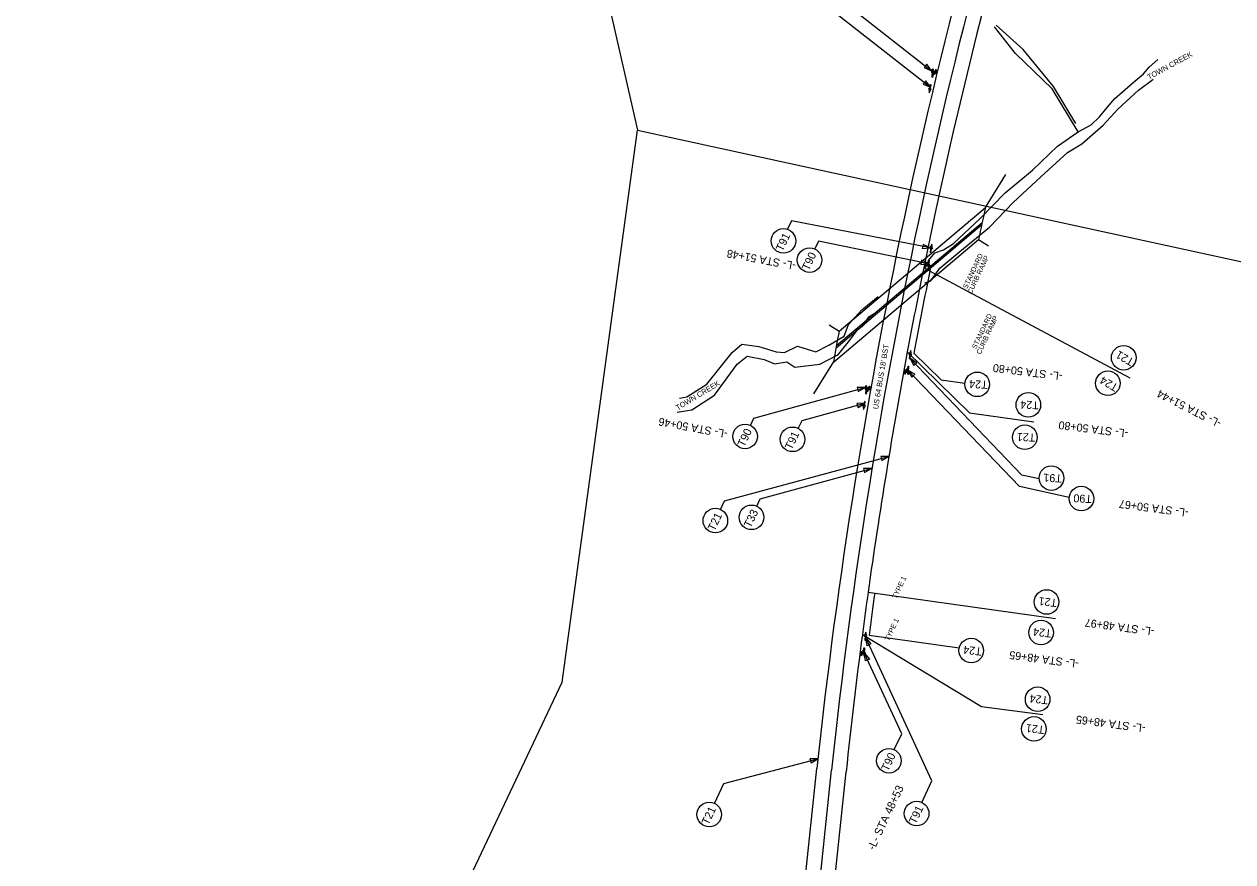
# Model space of a CAD drawing. Extents: x 553958 to 562499, y 493978 to 516388.
# Drawn here: x 556547 to 557453, y 505302 to 505930 of the extents above; entities that cross this region are included whole.
import ezdxf

# ---------------------------------------------------------------- set-up
doc = ezdxf.new("R2010")
doc.units = 0
for name, color, linetype in [('Default', 7, 'Continuous'), ('Prop Approach Slab', 7, 'Continuous'), ('Prop Conc 4in Sidewalk', 7, 'Continuous'), ('Prop EOT', 7, 'Continuous'), ('Prop Erosion Rip Rap Class II Label', 7, 'Continuous'), ('Prop Guardrail', 7, 'Continuous'), ('Prop Guardrail Anchor Unit CELL', 7, 'Continuous'), ('Prop Horizontal Alignment Tick Small', 7, 'Continuous'), ('Prop Superelevation Label', 7, 'Continuous'), ('Raster_Level_0', 7, 'Continuous'), ('Sheet Plan CELL', 7, 'Continuous'), ('Sheet Plot Border Inside CELL', 7, 'Continuous')]:
    doc.layers.add(name, color=color, linetype=linetype)

msp = doc.modelspace()

# ---------------------------------------------------------------- linework, layer by layer
at = {"layer": 'Default'}
for p, q in [((557267.43, 505792.37), (557282.76, 505817.09)), ((557157.69, 505699.67), (557267.43, 505792.37)), ((557155.38, 505687.25), (557264.62, 505779.52)), ((557155.67, 505688.8), (557264.96, 505781.12)), ((557153.4, 505676.41), (557262.19, 505768.31)), ((557262.19, 505768.31), (557269.79, 505763.6)), ((557150.22, 505704.3), (557157.69, 505699.67)), ((557138.72, 505652.73), (557153.4, 505676.41))]:
    msp.add_line(p, q, dxfattribs=at)
for centre, radius, start, end in [((561145.87, 504935.36), 3972, 167.53963, 167.89484), ((561116.74, 504957.58), 4028, 169.38359, 169.72001)]:
    msp.add_arc(centre, radius, start, end, dxfattribs=at)
at = {"layer": 'Prop Approach Slab'}
for p, q in [((557121.98, 505782.31), (557118.98, 505775.98)), ((557226.11, 505762.03), (557121.98, 505782.31)), ((557142.28, 505767.11), (557139.49, 505761.21)), ((557223.63, 505750.23), (557142.28, 505767.11)), ((557221.13, 505747.07), (557375.74, 505664.58)), ((557208.83, 505684.06), (557255.39, 505638.46)), ((557213.75, 505683.15), (557234.23, 505663.09)), ((557234.23, 505663.09), (557252.07, 505660.57)), ((557255.39, 505638.46), (557303.67, 505631.65)), ((557179.45, 505503.99), (557319.85, 505484.2)), ((557175.16, 505472.41), (557264.56, 505418.34)), ((557180.12, 505471.76), (557247.75, 505462.22)), ((557264.56, 505418.34), (557310.51, 505412.3))]:
    msp.add_line(p, q, dxfattribs=at)
at = {"layer": 'Prop EOT'}
for centre, start, end in [((561130.03, 504951.7), 168.49878, 169.42078), ((561134.93, 504950.71), 168.49878, 169.41963), ((561130.03, 504951.7), 172.04172, 172.49947), ((561134.99, 504951.05), 172.04229, 172.49947)]:
    msp.add_arc(centre, 3989, start, end, dxfattribs=at)
at = {"layer": 'Prop Erosion Rip Rap Class II Label'}
for points in [[(557510.24, 505740.54), (557854.59, 506431.05), (557889.73, 506539.36), (557425.46, 506933.59), (557046.6, 506628.46), (556899.98, 506318.25), (557006.57, 505850.3)], [(556922.59, 504396.31), (556546.8, 504844.44), (556803.39, 505126.33), (556950.01, 505436.53), (557006.57, 505850.3), (557510.24, 505740.54), (557485.82, 505175.14), (557082.56, 504320.7)]]:
    msp.add_lwpolyline(points, close=True, dxfattribs=at)
at = {"layer": 'Prop Guardrail'}
msp.add_line((557329.01, 505833.44), (557339.73, 505839.98), dxfattribs=at)
for points in [[(557335.2, 505855.15), (557318.48, 505882.86), (557295.62, 505910.67), (557275.53, 505929.04)], [(557224.65, 505752.62), (557229.44, 505758.43), (557236.01, 505760.45), (557243.43, 505765.25), (557263.41, 505784.12), (557282.31, 505803.32), (557302.6, 505820.21), (557321.39, 505838.21), (557336.85, 505849.11), (557317.41, 505881.09), (557290.05, 505907.77), (557274.13, 505927.57)], [(557336.85, 505849.11), (557346.59, 505854.26), (557352.92, 505860.11), (557358.68, 505867.34), (557364.34, 505874.04), (557370.09, 505879.01), (557378.2, 505886.08), (557382.54, 505889.59), (557385.91, 505892.34), (557390.17, 505897.4), (557396.51, 505903.31)], [(557339.73, 505839.98), (557355.53, 505854.05), (557366.65, 505865.91), (557382.17, 505880.3), (557392.8, 505888.25), (557393.19, 505888.6)], [(557221.92, 505735.81), (557226.55, 505737.34), (557233.13, 505746.89), (557248.24, 505759.3), (557270.35, 505777.55), (557288.27, 505795.98), (557308.94, 505815.28), (557329.01, 505833.44)], [(557077.55, 505683.54), (557084.84, 505689.76), (557097.49, 505688.05), (557110.48, 505684.17), (557116.79, 505683.52), (557126.52, 505688.35), (557140.16, 505684.2), (557150.11, 505689.11), (557161.38, 505695.79), (557164.82, 505704.7), (557169.67, 505710.11), (557174.65, 505715.49), (557186.92, 505725.65)], [(557081.24, 505674.86), (557088.86, 505680.94), (557101.51, 505678.39), (557109.34, 505675.15), (557118.47, 505676.53), (557124.62, 505672.58), (557143.22, 505674.95), (557156.24, 505681.56), (557156.45, 505681.36), (557165.79, 505692.89), (557171.41, 505700.52), (557176.2, 505704.36), (557179.88, 505710.38), (557184.61, 505713.09)], [(557036.33, 505638.98), (557047.2, 505640.77), (557064.25, 505651.6), (557081.24, 505674.86)], [(557038.03, 505649.41), (557043.56, 505650.32), (557058.48, 505659.79), (557077.55, 505683.54)]]:
    msp.add_lwpolyline(points, dxfattribs=at)
at = {"layer": 'Prop Horizontal Alignment Tick Small'}
for p, q in [((557227.05, 505894.79), (557227.28, 505894.73)), ((557227.05, 505894.79), (557227.28, 505894.73)), ((557227.46, 505891.19), (557227.73, 505892.84)), ((557227.73, 505892.84), (557228.87, 505894.62)), ((557228, 505892.58), (557227.82, 505891.5)), ((557227.82, 505891.5), (557228.95, 505892.29)), ((557229.07, 505894.5), (557228, 505892.81)), ((557228, 505892.81), (557228.77, 505892.95)), ((557229, 505892.75), (557228, 505892.58)), ((557228.08, 505894.55), (557228.32, 505894.49)), ((557228.08, 505894.55), (557228.32, 505894.49)), ((557228.77, 505892.95), (557228.78, 505893.6)), ((557228.78, 505893.6), (557229.02, 505893.59)), ((557228.87, 505894.62), (557229.08, 505894.52)), ((557228.95, 505892.29), (557228.88, 505891.99)), ((557229.02, 505893.59), (557229, 505892.75)), ((557229.43, 505894.24), (557229.67, 505894.18)), ((557229.43, 505894.24), (557229.67, 505894.18)), ((557230.46, 505894), (557230.7, 505893.95)), ((557230.46, 505894), (557230.7, 505893.95)), ((557227.21, 505890.7), (557227.06, 505890.74)), ((557227.21, 505890.7), (557227.06, 505890.74)), ((557227.78, 505891.21), (557227.46, 505891.19)), ((557228.88, 505891.99), (557227.78, 505891.21)), ((557228.16, 505890.49), (557228.01, 505890.52)), ((557228.16, 505890.49), (557228.01, 505890.52)), ((557222.24, 505748.91), (557222, 505748.95)), ((557222.24, 505748.91), (557222, 505748.95)), ((557223.28, 505748.72), (557223.04, 505748.77)), ((557223.28, 505748.72), (557223.04, 505748.77)), ((557223.63, 505750.23), (557224.62, 505750.46)), ((557223.66, 505749.39), (557223.63, 505750.23)), ((557223.86, 505748.37), (557223.64, 505748.46)), ((557224.75, 505751.54), (557223.66, 505750.69)), ((557223.66, 505750.69), (557223.72, 505750.99)), ((557223.66, 505748.48), (557224.64, 505750.22)), ((557223.9, 505749.4), (557223.66, 505749.39)), ((557223.72, 505750.99), (557224.78, 505751.83)), ((557224.9, 505750.21), (557223.86, 505748.37)), ((557224.64, 505750.22), (557223.88, 505750.05)), ((557223.88, 505750.05), (557223.9, 505749.4)), ((557224.37, 505752.53), (557224.52, 505752.51)), ((557224.37, 505752.53), (557224.52, 505752.51)), ((557224.64, 505748.48), (557224.4, 505748.52)), ((557224.64, 505748.48), (557224.4, 505748.52)), ((557224.62, 505750.46), (557224.75, 505751.54)), ((557224.78, 505751.83), (557225.1, 505751.86)), ((557225.1, 505751.86), (557224.9, 505750.21)), ((557225.33, 505752.36), (557225.48, 505752.34)), ((557225.33, 505752.36), (557225.48, 505752.34)), ((557225.69, 505748.29), (557225.45, 505748.34)), ((557225.69, 505748.29), (557225.45, 505748.34)), ((557206.92, 505669.12), (557206.68, 505669.16)), ((557206.92, 505669.12), (557206.68, 505669.16)), ((557207.97, 505668.95), (557207.73, 505668.99)), ((557207.97, 505668.95), (557207.73, 505668.99)), ((557208.3, 505670.46), (557209.29, 505670.69)), ((557208.34, 505669.62), (557208.3, 505670.46)), ((557209.41, 505671.78), (557208.33, 505670.92)), ((557208.33, 505670.92), (557208.38, 505671.22)), ((557208.55, 505668.6), (557208.33, 505668.69)), ((557208.58, 505669.63), (557208.34, 505669.62)), ((557208.35, 505668.71), (557209.31, 505670.46)), ((557208.38, 505671.22), (557209.43, 505672.07)), ((557209.31, 505670.46), (557208.55, 505670.28)), ((557209.58, 505670.45), (557208.55, 505668.6)), ((557208.55, 505670.28), (557208.58, 505669.63)), ((557209.01, 505672.77), (557209.16, 505672.75)), ((557209.01, 505672.77), (557209.16, 505672.75)), ((557209.33, 505668.72), (557209.09, 505668.76)), ((557209.33, 505668.72), (557209.09, 505668.76)), ((557209.29, 505670.69), (557209.41, 505671.78)), ((557209.43, 505672.07), (557209.75, 505672.11)), ((557209.75, 505672.11), (557209.58, 505670.45)), ((557209.97, 505672.61), (557210.12, 505672.58)), ((557209.97, 505672.61), (557210.12, 505672.58)), ((557210.38, 505668.55), (557210.14, 505668.59)), ((557210.38, 505668.55), (557210.14, 505668.59)), ((557177.18, 505657.42), (557177.42, 505657.38)), ((557177.18, 505657.42), (557177.42, 505657.38)), ((557177.98, 505655.52), (557179, 505657.37)), ((557178.22, 505657.25), (557178.46, 505657.21)), ((557178.22, 505657.25), (557178.46, 505657.21)), ((557179.21, 505657.26), (557178.25, 505655.51)), ((557179, 505657.37), (557179.22, 505657.28)), ((557179.59, 505657.02), (557179.83, 505656.98)), ((557179.59, 505657.02), (557179.83, 505656.98)), ((557180.64, 505656.85), (557180.88, 505656.81)), ((557180.64, 505656.85), (557180.88, 505656.81)), ((557177.58, 505653.36), (557177.43, 505653.39)), ((557177.58, 505653.36), (557177.43, 505653.39)), ((557177.8, 505653.86), (557177.98, 505655.52)), ((557178.13, 505653.9), (557177.8, 505653.86)), ((557179.18, 505654.75), (557178.13, 505653.9)), ((557178.27, 505655.28), (557178.15, 505654.19)), ((557178.15, 505654.19), (557179.23, 505655.05)), ((557178.25, 505655.51), (557179.01, 505655.69)), ((557179.25, 505655.51), (557178.27, 505655.28)), ((557178.54, 505653.2), (557178.39, 505653.22)), ((557178.54, 505653.2), (557178.39, 505653.22)), ((557178.98, 505656.34), (557179.21, 505656.35)), ((557179.01, 505655.69), (557178.98, 505656.34)), ((557179.23, 505655.05), (557179.18, 505654.75)), ((557179.21, 505656.35), (557179.25, 505655.51)), ((557174.01, 505457.97), (557173.77, 505458)), ((557174.01, 505457.97), (557173.77, 505458)), ((557175.06, 505457.84), (557174.82, 505457.87)), ((557175.06, 505457.84), (557174.82, 505457.87)), ((557175.33, 505459.37), (557176.31, 505459.65)), ((557175.41, 505458.53), (557175.33, 505459.37)), ((557176.37, 505460.74), (557175.34, 505459.83)), ((557175.34, 505459.83), (557175.37, 505460.13)), ((557175.37, 505460.13), (557176.38, 505461.02)), ((557175.64, 505458.55), (557175.41, 505458.53)), ((557175.66, 505457.52), (557175.44, 505457.6)), ((557175.45, 505457.62), (557176.33, 505459.41)), ((557176.33, 505459.41), (557175.59, 505459.2)), ((557175.59, 505459.2), (557175.64, 505458.55)), ((557176.6, 505459.41), (557175.66, 505457.52)), ((557175.93, 505461.71), (557176.09, 505461.69)), ((557175.93, 505461.71), (557176.09, 505461.69)), ((557176.44, 505457.68), (557176.2, 505457.71)), ((557176.44, 505457.68), (557176.2, 505457.71)), ((557176.31, 505459.65), (557176.37, 505460.74)), ((557176.38, 505461.02), (557176.7, 505461.08)), ((557176.7, 505461.08), (557176.6, 505459.41)), ((557176.9, 505461.59), (557177.05, 505461.57)), ((557176.9, 505461.59), (557177.05, 505461.57)), ((557177.49, 505457.55), (557177.25, 505457.58)), ((557177.49, 505457.55), (557177.25, 505457.58))]:
    msp.add_line(p, q, dxfattribs=at)
for points in [[(557226.83, 505881.26), (557226.03, 505880.77), (557226.68, 505884.11), (557226.06, 505884.23), (557225.41, 505880.89), (557224.85, 505881.65), (557225.22, 505878.28)], [(557226.83, 505881.26), (557226.03, 505880.77), (557226.68, 505884.11), (557226.06, 505884.23), (557225.41, 505880.89), (557224.85, 505881.65), (557225.22, 505878.28)], [(557225.71, 505761.78), (557226.51, 505762.28), (557225.86, 505758.94), (557226.48, 505758.82), (557227.13, 505762.15), (557227.69, 505761.4), (557227.32, 505764.77)], [(557225.71, 505761.78), (557226.51, 505762.28), (557225.86, 505758.94), (557226.48, 505758.82), (557227.13, 505762.15), (557227.69, 505761.4), (557227.32, 505764.77)], [(557209.97, 505682.05), (557210.75, 505682.57), (557210.24, 505679.21), (557210.87, 505679.12), (557211.38, 505682.48), (557211.96, 505681.75), (557211.45, 505685.1)], [(557209.97, 505682.05), (557210.75, 505682.57), (557210.24, 505679.21), (557210.87, 505679.12), (557211.38, 505682.48), (557211.96, 505681.75), (557211.45, 505685.1)], [(557177.52, 505643.92), (557176.74, 505643.4), (557177.3, 505646.75), (557176.67, 505646.86), (557176.11, 505643.51), (557175.53, 505644.25), (557176, 505640.89)], [(557177.52, 505643.92), (557176.74, 505643.4), (557177.3, 505646.75), (557176.67, 505646.86), (557176.11, 505643.51), (557175.53, 505644.25), (557176, 505640.89)], [(557176.47, 505471.02), (557177.22, 505471.58), (557176.87, 505468.2), (557177.5, 505468.13), (557177.86, 505471.51), (557178.48, 505470.81), (557177.81, 505474.13)], [(557176.47, 505471.02), (557177.22, 505471.58), (557176.87, 505468.2), (557177.5, 505468.13), (557177.86, 505471.51), (557178.48, 505470.81), (557177.81, 505474.13)]]:
    msp.add_lwpolyline(points, close=True, dxfattribs=at)
for centre, radius, start, end in [((557227.61, 505890.61), 0.563, 167.06052, 347.06052), ((557227.61, 505890.61), 0.563, 167.06052, 347.06052), ((557227.61, 505890.61), 0.41, 347.06052, 167.06052), ((557224.92, 505752.44), 0.563, 349.86585, 169.86585), ((557224.92, 505752.44), 0.563, 349.86585, 169.86585), ((557224.92, 505752.44), 0.41, 169.86585, 349.86585), ((557209.57, 505672.68), 0.563, 350.49881, 170.49881), ((557209.57, 505672.68), 0.563, 350.49881, 170.49881), ((557209.57, 505672.68), 0.41, 170.49881, 350.49881), ((557177.99, 505653.29), 0.563, 170.49881, 350.49881), ((557177.99, 505653.29), 0.563, 170.49881, 350.49881), ((557177.99, 505653.29), 0.41, 350.49881, 170.49881), ((557176.49, 505461.64), 0.563, 353.09103, 173.09103), ((557176.49, 505461.64), 0.563, 353.09103, 173.09103), ((557176.49, 505461.64), 0.41, 173.09103, 353.09103)]:
    msp.add_arc(centre, radius, start, end, dxfattribs=at)
for centre, major_axis, ratio, start_param, end_param in [((557227.68, 505894.64), (0.33, 1.46), 0.435841, 1.570796, 4.712389), ((557227.68, 505894.64), (0.33, 1.46), 0.435841, 4.712389, 7.853982), ((557227.68, 505894.64), (0.28, 1.22), 0.325967, 1.570796, 4.712389), ((557227.68, 505894.64), (0.28, 1.22), 0.325967, 4.712389, 7.853982), ((557230.07, 505894.09), (0.33, 1.46), 0.435841, 1.570796, 4.712389), ((557230.07, 505894.09), (0.33, 1.46), 0.435841, 4.712389, 7.853982), ((557230.07, 505894.09), (0.28, 1.22), 0.325967, 1.570796, 4.712389), ((557230.07, 505894.09), (0.28, 1.22), 0.325967, 4.712389, 7.853982), ((557222.64, 505748.84), (-0.26, -1.47), 0.435841, 4.712389, 7.853982), ((557222.64, 505748.84), (-0.26, -1.47), 0.435841, 1.570796, 4.712389), ((557222.64, 505748.84), (-0.22, -1.23), 0.325967, 4.712389, 7.853982), ((557222.64, 505748.84), (-0.22, -1.23), 0.325967, 1.570796, 4.712389), ((557225.04, 505748.41), (-0.26, -1.47), 0.435841, 4.712389, 7.853982), ((557225.04, 505748.41), (-0.26, -1.47), 0.435841, 1.570796, 4.712389), ((557225.04, 505748.41), (-0.22, -1.23), 0.325967, 4.712389, 7.853982), ((557225.04, 505748.41), (-0.22, -1.23), 0.325967, 1.570796, 4.712389), ((557207.32, 505669.06), (-0.25, -1.47), 0.435841, 4.712389, 7.853982), ((557207.32, 505669.06), (-0.25, -1.47), 0.435841, 1.570796, 4.712389), ((557207.32, 505669.06), (-0.21, -1.23), 0.325967, 4.712389, 7.853982), ((557207.32, 505669.06), (-0.21, -1.23), 0.325967, 1.570796, 4.712389), ((557209.74, 505668.65), (-0.25, -1.47), 0.435841, 4.712389, 7.853982), ((557209.74, 505668.65), (-0.25, -1.47), 0.435841, 1.570796, 4.712389), ((557209.74, 505668.65), (-0.21, -1.23), 0.325967, 4.712389, 7.853982), ((557209.74, 505668.65), (-0.21, -1.23), 0.325967, 1.570796, 4.712389), ((557177.82, 505657.32), (0.25, 1.47), 0.435841, 1.570796, 4.712389), ((557177.82, 505657.32), (0.25, 1.47), 0.435841, 4.712389, 7.853982), ((557177.82, 505657.32), (0.21, 1.23), 0.325967, 1.570796, 4.712389), ((557177.82, 505657.32), (0.21, 1.23), 0.325967, 4.712389, 7.853982), ((557180.23, 505656.91), (0.25, 1.47), 0.435841, 1.570796, 4.712389), ((557180.23, 505656.91), (0.25, 1.47), 0.435841, 4.712389, 7.853982), ((557180.23, 505656.91), (0.21, 1.23), 0.325967, 1.570796, 4.712389), ((557180.23, 505656.91), (0.21, 1.23), 0.325967, 4.712389, 7.853982), ((557174.41, 505457.92), (-0.18, -1.48), 0.435841, 4.712389, 7.853982), ((557174.41, 505457.92), (-0.18, -1.48), 0.435841, 1.570796, 4.712389), ((557174.41, 505457.92), (-0.15, -1.24), 0.325967, 4.712389, 7.853982), ((557174.41, 505457.92), (-0.15, -1.24), 0.325967, 1.570796, 4.712389), ((557176.84, 505457.63), (-0.18, -1.48), 0.435841, 4.712389, 7.853982), ((557176.84, 505457.63), (-0.18, -1.48), 0.435841, 1.570796, 4.712389), ((557176.84, 505457.63), (-0.15, -1.24), 0.325967, 4.712389, 7.853982), ((557176.84, 505457.63), (-0.15, -1.24), 0.325967, 1.570796, 4.712389)]:
    msp.add_ellipse(centre, major_axis=major_axis, ratio=ratio, start_param=start_param, end_param=end_param, dxfattribs=at)
at = {"layer": 'Raster_Level_0'}
msp.add_line((557110.08, 504972.34), (557152.03, 505370.68), dxfattribs=at)
msp.add_arc((561130.03, 504951.7), 4000, 161.63616, 173.98751, dxfattribs=at)
at = {"layer": 'Sheet Plan CELL'}
for points in [[(557148.39, 505963.62), (557141.4, 505948.88), (557226.34, 505882.38)], [(557173.37, 505958.65), (557165.84, 505942.7), (557227.05, 505894.79)], [(557307.66, 505588.94), (557294.62, 505591.77), (557210.87, 505679.12)], [(557330.14, 505575.04), (557293.01, 505583.1), (557209.27, 505670.45)], [(557091.19, 505629.05), (557093.75, 505634.47), (557177.18, 505657.42)], [(557126.99, 505626.77), (557129.91, 505632.57), (557177.1, 505645.56)], [(557068.88, 505566.04), (557071.87, 505572.6), (557195.02, 505605.77)], [(557095.97, 505568.45), (557098.53, 505573.87), (557181.96, 505596.83)], [(557219.78, 505346.48), (557227.34, 505362.57), (557177.68, 505469.82)], [(557199.01, 505386.04), (557204.64, 505397.85), (557176.56, 505458.51)], [(557064.3, 505345.77), (557071.37, 505360.72), (557141.86, 505379.03)]]:
    msp.add_lwpolyline(points, dxfattribs=at)
for points in [[(557221.53, 505897.14), (557227.05, 505894.79), (557223.44, 505899.58)], [(557220.82, 505884.73), (557226.34, 505882.38), (557222.74, 505887.18)], [(557220.07, 505761.63), (557226.05, 505762.07), (557220.65, 505764.68)], [(557218.88, 505749.69), (557224.85, 505750.25), (557219.4, 505752.75)], [(557216, 505676.01), (557210.87, 505679.12), (557213.76, 505673.86)], [(557214.4, 505667.34), (557209.27, 505670.45), (557212.16, 505665.19)], [(557172, 505654.39), (557177.18, 505657.42), (557171.18, 505657.38)], [(557171.93, 505642.53), (557177.1, 505645.56), (557171.1, 505645.52)], [(557189.83, 505602.76), (557195.02, 505605.77), (557189.02, 505605.76)], [(557176.78, 505593.79), (557181.96, 505596.83), (557175.96, 505596.79)], [(557178.71, 505463.91), (557177.68, 505469.82), (557181.53, 505465.22)], [(557177.58, 505452.6), (557176.56, 505458.51), (557180.4, 505453.9)], [(557136.64, 505376.07), (557141.86, 505379.03), (557135.86, 505379.07)]]:
    msp.add_lwpolyline(points, close=True, dxfattribs=at)
for centre in [(557115.99, 505767.26), (557135.55, 505752.87), (557371.05, 505679.72), (557261.25, 505659.76), (557359.18, 505660.58), (557299.56, 505644.4), (557087.25, 505620.72), (557122.79, 505618.57), (557296.93, 505620.15), (557316.86, 505589.54), (557339.35, 505574.17), (557064.94, 505557.7), (557092.03, 505560.12), (557313.23, 505496.69), (557309.09, 505473.8), (557256.76, 505460.3), (557306.55, 505423.79), (557303.74, 505401.58), (557195.05, 505377.72), (557060.36, 505337.44), (557215.82, 505338.16)]:
    msp.add_circle(centre, 9.22, dxfattribs=at)
at = {"layer": 'Sheet Plot Border Inside CELL'}
for p, q in [((557099.14, 504973.49), (557141.09, 505371.84)), ((557121.02, 504971.19), (557162.97, 505369.53))]:
    msp.add_line(p, q, dxfattribs=at)
for radius, start, end in [(4011, 161.63616, 173.98751), (3989, 161.63616, 168.49878), (3989, 169.42078, 172.04172), (3989, 172.49947, 173.98751)]:
    msp.add_arc((561130.03, 504951.7), radius, start, end, dxfattribs=at)

# ---------------------------------------------------------------- texts
at = {"layer": 'Prop Conc 4in Sidewalk'}
for s, p in [('STANDARD ', (557253.61, 505731.02)), ('CURB RAMP', (557257, 505727.08)), ('STANDARD ', (557260.39, 505685.85)), ('CURB RAMP', (557263.78, 505681.91)), ('TYPE 1', (557200.63, 505498.73)), ('TYPE 1', (557195.09, 505467.17))]:
    msp.add_text(s, height=3.75, rotation=64.7021, dxfattribs=at).set_placement(p)
at = {"layer": 'Prop EOT'}
for s, rotation, p in [('-L- STA 50+80', 172.94683, (557325.4, 505668.68)), ('T21', 177.11489, (557304.9, 505622.76))]:
    msp.add_text(s, height=6, rotation=rotation, dxfattribs=at).set_placement(p)
at = {"layer": 'Prop Guardrail Anchor Unit CELL'}
for rotation, p in [(28.68727, (557390.13, 505887.9)), (31.12584, (557036.73, 505640.12))]:
    msp.add_text('TOWN CREEK', height=4, rotation=rotation, dxfattribs=at).set_placement(p)
at = {"layer": 'Prop Superelevation Label'}
msp.add_text("US 64 BUS 18' BST", height=4, rotation=80.46212, dxfattribs=at).set_placement((557186.89, 505640.9))
at = {"layer": 'Sheet Plan CELL'}
for s, rotation, p in [('T91', 64.7021, (557115.36, 505758.9)), ('-L- STA 51+48', 169.42079, (557125.67, 505751.32)), ('T90', 64.7021, (557134.92, 505744.51)), ('T21', 149.94138, (557379.33, 505678.4)), ('T24', 177.11489, (557269.22, 505662.36)), ('T24', 149.94138, (557367.46, 505659.25)), ('T24', 177.11489, (557307.52, 505647)), ('-L- STA 51+44', 153.38092, (557444.85, 505632.5)), ('-L- STA 50+46', 169.42079, (557074.5, 505625.32)), ('-L- STA 50+80', 172.94683, (557374.64, 505625.84)), ('T90', 64.7021, (557086.62, 505612.36)), ('T91', 64.7021, (557122.16, 505610.21)), ('T91', 177.11489, (557324.83, 505592.14)), ('T90', 177.11489, (557347.32, 505576.77)), ('-L- STA 50+67', 172.50087, (557419.94, 505566.38)), ('T21', 64.7021, (557064.31, 505549.34)), ('T33', 64.7021, (557091.4, 505551.76)), ('T21', 173.58886, (557321.35, 505498.8)), ('T24', 173.58886, (557317.2, 505475.91)), ('-L- STA 48+97', 172.50087, (557394.35, 505477.39)), ('T24', 173.58886, (557264.87, 505462.4)), ('-L- STA 48+65', 172.50087, (557337.68, 505453.16)), ('T24', 173.58886, (557314.66, 505425.9)), ('T21', 173.58886, (557311.86, 505403.69)), ('-L- STA 48+65', 172.50087, (557387.65, 505404.86)), ('T90', 64.7021, (557194.42, 505369.36)), ('-L- STA 48+53', 64.7021, (557183.97, 505310.16)), ('T21', 64.7021, (557059.73, 505329.08)), ('T91', 64.7021, (557215.18, 505329.8))]:
    msp.add_text(s, height=6, rotation=rotation, dxfattribs=at).set_placement(p)

doc.saveas('drawing.dxf')
